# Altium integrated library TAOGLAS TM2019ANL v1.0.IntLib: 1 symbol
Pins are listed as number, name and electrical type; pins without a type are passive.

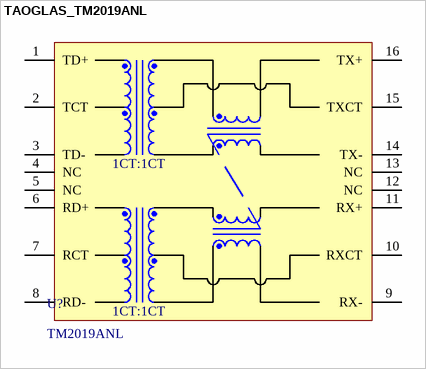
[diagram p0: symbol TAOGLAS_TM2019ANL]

## TAOGLAS_TM2019ANL
designator U?, comment TM2019ANL
10/100 Base-T transformer Single Port and 16pin SMT with PoE; ComponentLibStatus: Created; MFG: Taoglas; Temp_High: +85C; Temp_Low: -40C
footprint TAOGLAS_TM2019ANL (10/100 Base-T transformer Single Port and 16pin SMT with PoE)
pins: 1 TD+, 2 TCT, 3 TD-, 4 NC, 5 NC, 6 RD+, 7 RCT, 8 RD-, 9 RX-, 10 RXCT, 11 RX+, 12 NC, 13 NC, 14 TX-, 15 TXCT, 16 TX+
